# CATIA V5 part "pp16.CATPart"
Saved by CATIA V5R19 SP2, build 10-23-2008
Part number: pp16
Publications: "Line.1", "Line.2", "Line.3", "Plane.1", "Plane.2", "Line.4", "Vertex", "Plane.3", "Sketch.1"
Bounding box of the stored display mesh (mm): x 0 to 10, y -422 to 0, z 0 to 52
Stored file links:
  C:\Users\Welcome\Documents\thinkm2\pp16.CATPart
  C:\Users\Welcome\Documents\thinkm2\Brasmeca.CATProduct
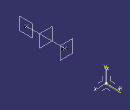
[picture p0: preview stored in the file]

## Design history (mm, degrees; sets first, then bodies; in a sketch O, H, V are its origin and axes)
AxisSystem1: origin (0, 0, 0), X (1, 0, 0), Y (0, 1, 0), Z (0, 0, 1)
Set1
  Point1: linked copy from another document
  Point2: linked copy from another document
Body1 (main body)
  Line1: type PtPt, FirstPoint Point1, SecondPoint Point2
  Line2: type PtDir, RefPoint Point1, Direction edge [XY plane of AxisSystem1 | ZX plane of AxisSystem1], Start 0, End 10
  Line3: type PtDir, RefPoint Point2, Direction edge [XY plane of AxisSystem1 | ZX plane of AxisSystem1], Start 0, End 10
  Plane1: type Normal, Curve Line3
  Line4: type PtDir, RefPoint Point1, Direction edge [YZ plane of AxisSystem1 | XY plane of AxisSystem1], Start 0, End 10
  Plane2: type Normal, Curve Line4, RefPoint vertex of Line4
  Plane3: type Normal, Curve Line1
  Sketch1 on Plane1, origin (5, 0, 0), H (0, 1, 0), V (0, 0, 1)
    circle A1 centre (-420, 50) radius 2
    reference projected point E1 (-420, 50) from Line3
    radius A1 = 2
    distance A1 E1 = 2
